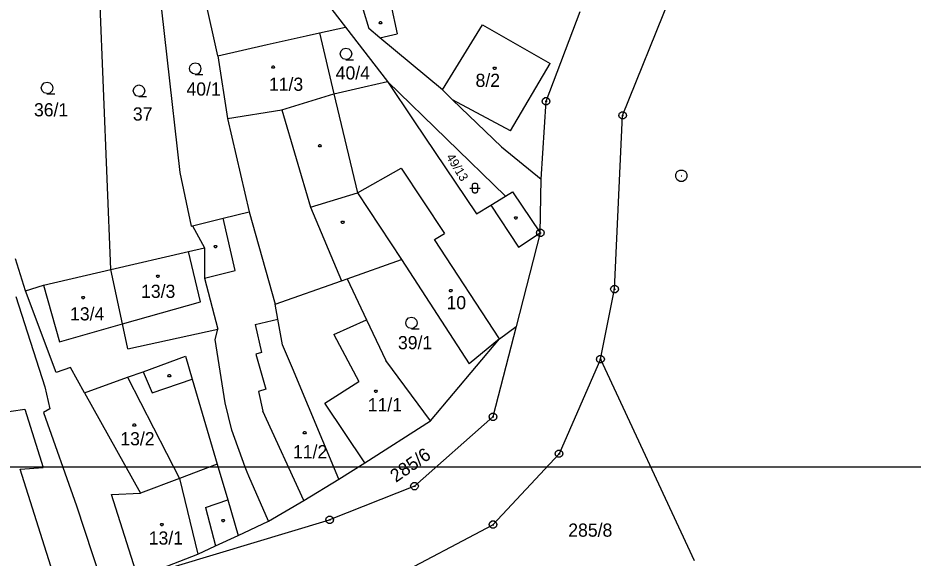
# Model space of a CAD drawing. Extents: x -779723 to -777378, y -1011169 to -1009297.
# Drawn here: x -779102 to -778986.4, y -1010279.6 to -1010209.9 of the extents above; entities that cross this region are included whole.
import ezdxf

# ---------------------------------------------------------------- set-up
doc = ezdxf.new("R2010")
doc.units = 0
for name, color, linetype in [('Default', 7, 'Continuous'), ('KN_HRANICE', 7, 'Continuous'), ('KN_KULTURY', 7, 'Continuous'), ('KN_PARCELY', 7, 'Continuous'), ('KN_SLUCKY', 7, 'Continuous'), ('LEGENDA', 7, 'Continuous')]:
    doc.layers.add(name, color=color, linetype=linetype)

# ---------------------------------------------------------------- blocks, each defined once
blk = doc.blocks.new('101')
at = {"layer": 'Default'}
blk.add_line((-0.05, 0), (0.05, 0), dxfattribs=at)
blk.add_lwpolyline([(0.19, 0.72), (0.53, 0.53), (0.72, 0.19), (0.72, -0.2), (0.53, -0.54), (0.19, -0.73), (-0.2, -0.73), (-0.54, -0.54), (-0.73, -0.2), (-0.73, 0.19), (-0.54, 0.53), (-0.2, 0.72), (0.19, 0.72)], dxfattribs=at)
blk = doc.blocks.new('304')
at = {"layer": 'Default'}
blk.add_lwpolyline([(0, 0), (-0.38, 0.1), (-0.65, 0.37), (-0.75, 0.74), (-0.65, 1.11), (-0.38, 1.38), (-0.01, 1.48), (0.36, 1.38), (0.63, 1.11), (0.73, 0.73), (0.63, 0.35), (0.36, 0.08), (-0.02, -0.02), (0.98, -0.02)], dxfattribs=at)
blk = doc.blocks.new('316')
at = {"layer": 'Default'}
for points in [[(-0.5, 1.5), (-0.4, 1.79), (-0.15, 1.97), (0.16, 1.97), (0.41, 1.79), (0.51, 1.5), (0.51, 0.5), (0.41, 0.21), (0.16, 0.03), (-0.15, 0.03), (-0.4, 0.21), (-0.5, 0.5), (-0.5, 1.5)], [(-1, 1), (0.27, 1), (1, 1)]]:
    blk.add_lwpolyline(points, dxfattribs=at)
blk = doc.blocks.new('402')
at = {"layer": 'Default'}
blk.add_lwpolyline([(0.09, 0.15), (0.18, 0), (0.09, -0.15), (-0.09, -0.15), (-0.18, 0), (-0.09, 0.15), (0.09, 0.15)], dxfattribs=at)
blk = doc.blocks.new('105')
at = {"layer": 'Default'}
blk.add_line((-0.12, 0), (0.12, 0), dxfattribs=at)
blk.add_lwpolyline([(0.15, 0.48), (0.4, 0.3), (0.5, 0.01), (0.4, -0.28), (0.15, -0.46), (-0.16, -0.46), (-0.41, -0.28), (-0.51, 0.01), (-0.41, 0.3), (-0.16, 0.48), (0.15, 0.48)], dxfattribs=at)

msp = doc.modelspace()

# ---------------------------------------------------------------- linework, layer by layer
at = {"layer": 'KN_HRANICE'}
for p, q in [((-779089.99, -1010242.37), (-779091.64, -1010201.91)), ((-779076.2, -1010214.76), (-779078.76, -1010203.29)), ((-779023.92, -1010222.47), (-779017.34, -1010206.13)), ((-779062.19, -1010207.85), (-779059.7, -1010211.07)), ((-779057.43, -1010208.85), (-779056.71, -1010211.24)), ((-779033.8, -1010220.65), (-779029.4, -1010209.06)), ((-779064.77, -1010212.2), (-779063.08, -1010211.82)), ((-779063.08, -1010211.82), (-779059.7, -1010211.07)), ((-779063.08, -1010211.82), (-779061.2, -1010219.69)), ((-779059.7, -1010211.07), (-779054.29, -1010218.08)), ((-779055.26, -1010212.45), (-779056.71, -1010211.24)), ((-779069.82, -1010213.33), (-779064.77, -1010212.2)), ((-779047.2, -1010219.18), (-779055.26, -1010212.45)), ((-779076.2, -1010214.76), (-779069.82, -1010213.33)), ((-779076.2, -1010214.76), (-779074.94, -1010222.88)), ((-779061.2, -1010219.69), (-779057.29, -1010218.78)), ((-779057.29, -1010218.78), (-779054.29, -1010218.08)), ((-779054.29, -1010218.08), (-779050.87, -1010223.15)), ((-779054.29, -1010218.08), (-779039.06, -1010232.9)), ((-779061.2, -1010219.69), (-779058.14, -1010232.46)), ((-779047.2, -1010219.18), (-779045.87, -1010220.45)), ((-779045.87, -1010220.45), (-779039.55, -1010226.53)), ((-779034.42, -1010230.71), (-779033.8, -1010220.65)), ((-779074.94, -1010222.88), (-779072.13, -1010234.9)), ((-779050.87, -1010223.15), (-779042.77, -1010235.17)), ((-779024.96, -1010244.9), (-779023.92, -1010222.47)), ((-779039.55, -1010226.53), (-779034.42, -1010230.71)), ((-779034.55, -1010237.65), (-779034.42, -1010230.71)), ((-779058.14, -1010232.46), (-779052.46, -1010241.08)), ((-779039.06, -1010232.9), (-779038.16, -1010232.35)), ((-779038.16, -1010232.35), (-779034.55, -1010237.65)), ((-779040.92, -1010234.04), (-779039.06, -1010232.9)), ((-779075.52, -1010235.75), (-779072.13, -1010234.9)), ((-779072.13, -1010234.9), (-779068.8, -1010246.85)), ((-779042.77, -1010235.17), (-779040.92, -1010234.04)), ((-779079.48, -1010236.74), (-779075.52, -1010235.75)), ((-779079.62, -1010236.77), (-779079.48, -1010236.74)), ((-779079.48, -1010236.74), (-779077.92, -1010239.59)), ((-779034.55, -1010237.65), (-779037.66, -1010249.73)), ((-779079.97, -1010240.06), (-779077.92, -1010239.59)), ((-779077.92, -1010239.59), (-779077.92, -1010243.48)), ((-779089.99, -1010242.37), (-779079.97, -1010240.06)), ((-779101.02, -1010245.11), (-779102.33, -1010241)), ((-779059.5, -1010243.56), (-779052.46, -1010241.08)), ((-779052.46, -1010241.08), (-779043.73, -1010254.53)), ((-779098.71, -1010244.39), (-779089.99, -1010242.37)), ((-779088.5, -1010249.4), (-779089.99, -1010242.37)), ((-779077.92, -1010243.48), (-779076.18, -1010250.09)), ((-779068.8, -1010246.85), (-779060.22, -1010243.82)), ((-779060.22, -1010243.82), (-779059.5, -1010243.56)), ((-779059.5, -1010243.56), (-779056.98, -1010248.86)), ((-779101.02, -1010245.11), (-779098.71, -1010244.39)), ((-779097.05, -1010255.65), (-779101.02, -1010245.11)), ((-779026.78, -1010253.95), (-779024.96, -1010244.9)), ((-779102.28, -1010245.85), (-779098.52, -1010257.5)), ((-779068.44, -1010248.79), (-779068.8, -1010246.85)), ((-779067.83, -1010252.08), (-779068.44, -1010248.79)), ((-779056.98, -1010248.86), (-779054.48, -1010254.13)), ((-779087.83, -1010252.59), (-779088.5, -1010249.4)), ((-779087.83, -1010252.59), (-779076.18, -1010250.09)), ((-779076.54, -1010251.4), (-779076.18, -1010250.09)), ((-779037.66, -1010249.73), (-779040.66, -1010261.41)), ((-779039.84, -1010251.3), (-779037.66, -1010249.73)), ((-779075.23, -1010259.6), (-779076.54, -1010251.4)), ((-779066.56, -1010255.1), (-779067.83, -1010252.08)), ((-779048.74, -1010261.92), (-779039.84, -1010251.3)), ((-779039.84, -1010251.3), (-779043.73, -1010254.53)), ((-779085.85, -1010255.56), (-779080.36, -1010253.56)), ((-779080.36, -1010253.56), (-779079.49, -1010256.51)), ((-779048.74, -1010261.92), (-779054.48, -1010254.13)), ((-779026.78, -1010253.95), (-779032.12, -1010266.16)), ((-779026.78, -1010253.95), (-779014.69, -1010279.95)), ((-779095.21, -1010255.03), (-779097.05, -1010255.65)), ((-779093.41, -1010258.3), (-779095.21, -1010255.03)), ((-779087.87, -1010256.29), (-779085.85, -1010255.56)), ((-779060.55, -1010269.44), (-779066.56, -1010255.1)), ((-779093.41, -1010258.3), (-779087.87, -1010256.29)), ((-779079.49, -1010256.51), (-779076.26, -1010267.51)), ((-779098.52, -1010257.5), (-779097.87, -1010260.36)), ((-779093.41, -1010258.3), (-779086.17, -1010271.27)), ((-779107.93, -1010261.36), (-779101.09, -1010260.41)), ((-779101.09, -1010260.41), (-779098.76, -1010267.92)), ((-779097.87, -1010260.36), (-779098.72, -1010260.84)), ((-779098.72, -1010260.84), (-779094.46, -1010272.88)), ((-779050.79, -1010270.34), (-779040.66, -1010261.41)), ((-779057.2, -1010267.35), (-779048.74, -1010261.92)), ((-779032.12, -1010266.16), (-779040.66, -1010275.32)), ((-779060.55, -1010269.44), (-779057.2, -1010267.35)), ((-779101.73, -1010268.16), (-779098.76, -1010267.92)), ((-779097.04, -1010282.96), (-779101.73, -1010268.16)), ((-779076.26, -1010267.51), (-779081.16, -1010269.37)), ((-779076.26, -1010267.51), (-779074.9, -1010272.13)), ((-779081.16, -1010269.37), (-779086.17, -1010271.27)), ((-779065.1, -1010272.18), (-779060.55, -1010269.44)), ((-779050.79, -1010270.34), (-779061.75, -1010274.71)), ((-779089.91, -1010271.43), (-779086.17, -1010271.27)), ((-779086.5, -1010282.14), (-779089.91, -1010271.43)), ((-779094.46, -1010272.88), (-779091.27, -1010282.5)), ((-779074.9, -1010272.13), (-779073.55, -1010276.72)), ((-779069.64, -1010274.85), (-779065.1, -1010272.18)), ((-779086.5, -1010282.14), (-779061.75, -1010274.71)), ((-779073.55, -1010276.72), (-779069.64, -1010274.85)), ((-779058.07, -1010284.48), (-779040.66, -1010275.32)), ((-779076.48, -1010278.07), (-779073.55, -1010276.72)), ((-779078.75, -1010279.13), (-779076.48, -1010278.07)), ((-779086.5, -1010282.14), (-779078.75, -1010279.13))]:
    msp.add_line(p, q, dxfattribs=at)
for points in [[(-779084.45, -1010200.01), (-779081.11, -1010229.82), (-779079.62, -1010236.77)], [(-779069.64, -1010274.85), (-779072.2, -1010269.07), (-779072.39, -1010268.55), (-779072.64, -1010267.9), (-779074.39, -1010263.13), (-779075.23, -1010259.6)]]:
    msp.add_lwpolyline(points, dxfattribs=at)
at = {"layer": 'KN_SLUCKY'}
for p, q in [((-779053.86, -1010208.15), (-779053.04, -1010211.92)), ((-779047.2, -1010219.18), (-779042.03, -1010210.78)), ((-779042.03, -1010210.78), (-779033.28, -1010215.75)), ((-779055.26, -1010212.45), (-779053.04, -1010211.92)), ((-779038.39, -1010224.47), (-779033.28, -1010215.75)), ((-779067.91, -1010221.73), (-779061.2, -1010219.69)), ((-779038.39, -1010224.47), (-779045.87, -1010220.45)), ((-779074.94, -1010222.88), (-779067.91, -1010221.73)), ((-779067.91, -1010221.73), (-779064.23, -1010234.32)), ((-779058.14, -1010232.46), (-779052.52, -1010229.28)), ((-779052.52, -1010229.28), (-779046.93, -1010237.71)), ((-779064.23, -1010234.32), (-779058.14, -1010232.46)), ((-779064.23, -1010234.32), (-779060.22, -1010243.82)), ((-779040.92, -1010234.04), (-779037.38, -1010239.5)), ((-779048.2, -1010238.48), (-779046.93, -1010237.71)), ((-779039.84, -1010251.3), (-779048.2, -1010238.48)), ((-779037.38, -1010239.5), (-779034.55, -1010237.65)), ((-779078.41, -1010246.55), (-779079.97, -1010240.06)), ((-779098.71, -1010244.39), (-779096.62, -1010251.69)), ((-779088.5, -1010249.4), (-779078.41, -1010246.55)), ((-779071.35, -1010249.46), (-779068.44, -1010248.79)), ((-779061.2, -1010250.75), (-779056.98, -1010248.86)), ((-779096.62, -1010251.69), (-779088.5, -1010249.4)), ((-779061.2, -1010250.75), (-779057.98, -1010256.83)), ((-779085.85, -1010255.56), (-779084.65, -1010258.28)), ((-779087.87, -1010256.29), (-779081.16, -1010269.37)), ((-779084.65, -1010258.28), (-779079.49, -1010256.51)), ((-779062.39, -1010259.63), (-779057.98, -1010256.83)), ((-779057.2, -1010267.35), (-779062.39, -1010259.63)), ((-779065.1, -1010272.18), (-779070.38, -1010260.68)), ((-779081.16, -1010269.37), (-779078.75, -1010279.13)), ((-779077.79, -1010273.1), (-779074.9, -1010272.13)), ((-779077.79, -1010273.1), (-779076.48, -1010278.07))]:
    msp.add_line(p, q, dxfattribs=at)
for points in [[(-779077.92, -1010243.48), (-779073.96, -1010242.51), (-779075.52, -1010235.75)], [(-779071.35, -1010249.46), (-779070.54, -1010253.09), (-779071.3, -1010253.31), (-779070, -1010257.83), (-779070.95, -1010258.14), (-779070.38, -1010260.68)]]:
    msp.add_lwpolyline(points, dxfattribs=at)
at = {"layer": 'LEGENDA'}
msp.add_lwpolyline([(-779530.66, -1010687.91), (-778936.66, -1010687.91), (-778936.66, -1010267.91), (-779530.66, -1010267.91)], close=True, dxfattribs=at)

# ---------------------------------------------------------------- block references
at = {"layer": 'KN_KULTURY'}
for name, p in [('402', (-779055.19, -1010210.5)), ('304', (-779059.63, -1010215.26)), ('304', (-779079.1, -1010217.16)), ('402', (-779069.04, -1010216.22)), ('402', (-779040.44, -1010216.37)), ('304', (-779098.23, -1010219.66)), ('304', (-779086.36, -1010220.02)), ('402', (-779063.03, -1010226.38)), ('402', (-779060.07, -1010236.27)), ('402', (-779037.72, -1010235.71)), ('402', (-779076.48, -1010239.41)), ('402', (-779083.93, -1010243.24)), ('402', (-779046.12, -1010245.08)), ('402', (-779093.58, -1010245.99)), ('304', (-779051.18, -1010250)), ('402', (-779082.45, -1010256.08)), ('402', (-779055.8, -1010258.09)), ('402', (-779086.97, -1010262.45)), ('402', (-779064.98, -1010263.45)), ('402', (-779083.41, -1010275.31)), ('402', (-779075.49, -1010274.79))]:
    msp.add_blockref(name, p, dxfattribs=at)
at = {"layer": 'KN_KULTURY', "xscale": 0.67, "yscale": 0.67}
msp.add_blockref('316', (-779042.98, -1010232.52), dxfattribs=at)
at = {"layer": 'KN_PARCELY'}
for name, p in [('105', (-779033.8, -1010220.65)), ('105', (-779023.92, -1010222.47)), ('101', (-779016.33, -1010230.26)), ('105', (-779034.55, -1010237.65)), ('105', (-779024.96, -1010244.9)), ('105', (-779026.78, -1010253.95)), ('105', (-779040.66, -1010261.41)), ('105', (-779032.12, -1010266.16)), ('105', (-779050.79, -1010270.34)), ('105', (-779061.75, -1010274.71)), ('105', (-779040.66, -1010275.32))]:
    msp.add_blockref(name, p, dxfattribs=at)

# ---------------------------------------------------------------- texts
for s, p in [('40/4', (-779060.97, -1010217.83)), ('11/3', (-779069.59, -1010219.29)), ('8/2', (-779042.91, -1010218.79)), ('40/1', (-779080.24, -1010219.91)), ('36/1', (-779099.93, -1010222.59)), ('37', (-779087.16, -1010223.13)), ('13/3', (-779086.1, -1010246.03)), ('10', (-779046.66, -1010247.49)), ('13/4', (-779095.27, -1010248.94)), ('39/1', (-779052.93, -1010252.66)), ('11/1', (-779056.83, -1010260.68)), ('13/2', (-779088.78, -1010265.07)), ('11/2', (-779066.48, -1010266.75)), ('285/8', (-779030.94, -1010276.87)), ('13/1', (-779085.11, -1010277.89))]:
    msp.add_text(s, height=1.7, dxfattribs=at).set_placement(p)
for s, height, rotation, p in [('49/13', 1.14, 301.261, (-779046.74, -1010227.83)), ('285/6', 1.7, 35.008, (-779053.19, -1010269.93))]:
    msp.add_text(s, height=height, rotation=rotation, dxfattribs=at).set_placement(p)

doc.saveas('drawing.dxf')
